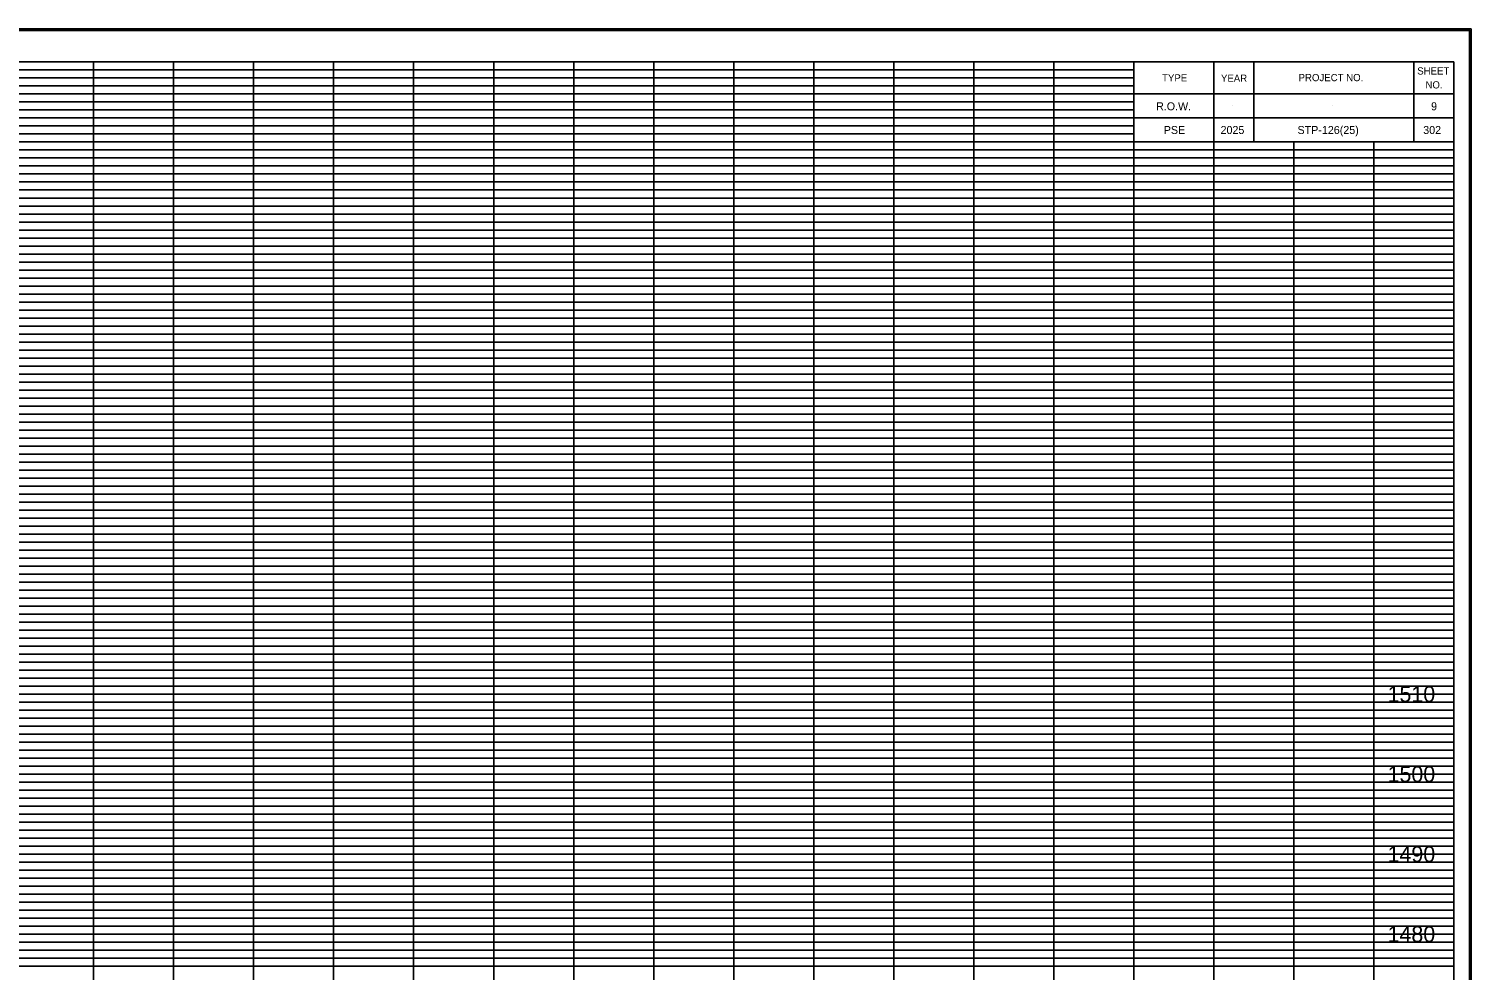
# Model space of a CAD drawing. Extents: x 980 to 2064, y 978 to 2267.
# Drawn here: x 1511.9 to 1692.2, y 1876.5 to 1994.1 of the extents above; entities that cross this region are included whole.
import ezdxf

# ---------------------------------------------------------------- set-up
doc = ezdxf.new("R2010")
doc.units = 0
for name, color, linetype in [('Default', 7, 'Continuous'), ('DESIGN - SCRATCH - User 1', 7, 'Continuous'), ('DESIGN - SHEET - Corner Text', 7, 'Continuous'), ('DESIGN - SHEET - Light Grid', 7, 'Continuous'), ('DESIGN - SHEET - Linework', 7, 'Continuous'), ('DESIGN - SHEET - Plot Shape', 7, 'Continuous')]:
    doc.layers.add(name, color=color, linetype=linetype)

# ---------------------------------------------------------------- blocks, each defined once
blk = doc.blocks.new('XSTSHT')
at = {"layer": 'DESIGN - SCRATCH - User 1'}
for p, q in [((28.5, 20.45), (28.5, 20.45)), ((29.24, 20.45), (29.24, 20.45)), ((30.49, 20.45), (30.49, 20.45)), ((31.74, 20.45), (31.74, 20.45)), ((28.5, 20.15), (28.5, 20.15)), ((29.24, 20.15), (29.24, 20.15)), ((30.49, 20.15), (30.49, 20.15)), ((31.74, 20.15), (31.74, 20.15))]:
    blk.add_line(p, q, dxfattribs=at)
at = {"layer": 'DESIGN - SHEET - Light Grid'}
for p, q in [((8, 20.9), (16, 20.9)), ((8, 20.8), (16, 20.8)), ((16, 20.9), (24, 20.9)), ((16, 20.8), (24, 20.8)), ((24, 20.9), (28, 20.9)), ((24, 20.8), (28, 20.8)), ((8, 20.7), (16, 20.7)), ((8, 20.6), (16, 20.6)), ((16, 20.7), (24, 20.7)), ((16, 20.6), (24, 20.6)), ((24, 20.7), (28, 20.7)), ((24, 20.6), (28, 20.6)), ((8, 20.5), (16, 20.5)), ((8, 20.4), (16, 20.4)), ((16, 20.5), (24, 20.5)), ((16, 20.4), (24, 20.4)), ((24, 20.5), (28, 20.5)), ((24, 20.4), (28, 20.4)), ((8, 20.3), (16, 20.3)), ((8, 20.2), (16, 20.2)), ((16, 20.3), (24, 20.3)), ((16, 20.2), (24, 20.2)), ((24, 20.3), (28, 20.3)), ((24, 20.2), (28, 20.2)), ((8, 20.1), (16, 20.1)), ((16, 20.1), (24, 20.1)), ((24, 20.1), (28, 20.1)), ((8, 19.9), (16, 19.9)), ((16, 19.9), (24, 19.9)), ((24, 19.9), (32, 19.9)), ((8, 19.8), (16, 19.8)), ((8, 19.7), (16, 19.7)), ((16, 19.8), (24, 19.8)), ((16, 19.7), (24, 19.7)), ((24, 19.8), (32, 19.8)), ((24, 19.7), (32, 19.7)), ((8, 19.6), (16, 19.6)), ((8, 19.5), (16, 19.5)), ((16, 19.6), (24, 19.6)), ((16, 19.5), (24, 19.5)), ((24, 19.6), (32, 19.6)), ((24, 19.5), (32, 19.5)), ((8, 19.4), (16, 19.4)), ((8, 19.3), (16, 19.3)), ((16, 19.4), (24, 19.4)), ((16, 19.3), (24, 19.3)), ((24, 19.4), (32, 19.4)), ((24, 19.3), (32, 19.3)), ((8, 19.2), (16, 19.2)), ((16, 19.2), (24, 19.2)), ((24, 19.2), (32, 19.2)), ((8, 19.1), (16, 19.1)), ((16, 19.1), (24, 19.1)), ((24, 19.1), (32, 19.1)), ((8, 18.9), (16, 18.9)), ((8, 18.8), (16, 18.8)), ((16, 18.9), (24, 18.9)), ((16, 18.8), (24, 18.8)), ((24, 18.9), (32, 18.9)), ((24, 18.8), (32, 18.8)), ((8, 18.7), (16, 18.7)), ((8, 18.6), (16, 18.6)), ((16, 18.7), (24, 18.7)), ((16, 18.6), (24, 18.6)), ((24, 18.7), (32, 18.7)), ((24, 18.6), (32, 18.6)), ((8, 18.5), (16, 18.5)), ((8, 18.4), (16, 18.4)), ((16, 18.5), (24, 18.5)), ((16, 18.4), (24, 18.4)), ((24, 18.5), (32, 18.5)), ((24, 18.4), (32, 18.4)), ((8, 18.3), (16, 18.3)), ((16, 18.3), (24, 18.3)), ((24, 18.3), (32, 18.3)), ((8, 18.2), (16, 18.2)), ((8, 18.1), (16, 18.1)), ((16, 18.2), (24, 18.2)), ((16, 18.1), (24, 18.1)), ((24, 18.2), (32, 18.2)), ((24, 18.1), (32, 18.1)), ((8, 17.9), (16, 17.9)), ((16, 17.9), (24, 17.9)), ((24, 17.9), (32, 17.9)), ((8, 17.8), (16, 17.8)), ((8, 17.7), (16, 17.7)), ((16, 17.8), (24, 17.8)), ((16, 17.7), (24, 17.7)), ((24, 17.8), (32, 17.8)), ((24, 17.7), (32, 17.7)), ((8, 17.6), (16, 17.6)), ((8, 17.5), (16, 17.5)), ((16, 17.6), (24, 17.6)), ((16, 17.5), (24, 17.5)), ((24, 17.6), (32, 17.6)), ((24, 17.5), (32, 17.5)), ((8, 17.4), (16, 17.4)), ((16, 17.4), (24, 17.4)), ((24, 17.4), (32, 17.4)), ((8, 17.3), (16, 17.3)), ((8, 17.2), (16, 17.2)), ((16, 17.3), (24, 17.3)), ((16, 17.2), (24, 17.2)), ((24, 17.3), (32, 17.3)), ((24, 17.2), (32, 17.2)), ((8, 17.1), (16, 17.1)), ((16, 17.1), (24, 17.1)), ((24, 17.1), (32, 17.1)), ((8, 16.9), (16, 16.9)), ((8, 16.8), (16, 16.8)), ((16, 16.9), (24, 16.9)), ((16, 16.8), (24, 16.8)), ((24, 16.9), (32, 16.9)), ((24, 16.8), (32, 16.8)), ((8, 16.7), (16, 16.7)), ((8, 16.6), (16, 16.6)), ((16, 16.7), (24, 16.7)), ((16, 16.6), (24, 16.6)), ((24, 16.7), (32, 16.7)), ((24, 16.6), (32, 16.6)), ((8, 16.5), (16, 16.5)), ((16, 16.5), (24, 16.5)), ((24, 16.5), (32, 16.5)), ((8, 16.4), (16, 16.4)), ((8, 16.3), (16, 16.3)), ((16, 16.4), (24, 16.4)), ((16, 16.3), (24, 16.3)), ((24, 16.4), (32, 16.4)), ((24, 16.3), (32, 16.3)), ((8, 16.2), (16, 16.2)), ((8, 16.1), (16, 16.1)), ((16, 16.2), (24, 16.2)), ((16, 16.1), (24, 16.1)), ((24, 16.2), (32, 16.2)), ((24, 16.1), (32, 16.1)), ((8, 15.9), (16, 15.9)), ((16, 15.9), (24, 15.9)), ((24, 15.9), (32, 15.9)), ((8, 15.8), (16, 15.8)), ((8, 15.7), (16, 15.7)), ((16, 15.8), (24, 15.8)), ((16, 15.7), (24, 15.7)), ((24, 15.8), (32, 15.8)), ((24, 15.7), (32, 15.7)), ((8, 15.6), (16, 15.6)), ((16, 15.6), (24, 15.6)), ((24, 15.6), (32, 15.6)), ((8, 15.5), (16, 15.5)), ((8, 15.4), (16, 15.4)), ((16, 15.5), (24, 15.5)), ((16, 15.4), (24, 15.4)), ((24, 15.5), (32, 15.5)), ((24, 15.4), (32, 15.4)), ((8, 15.3), (16, 15.3)), ((8, 15.2), (16, 15.2)), ((16, 15.3), (24, 15.3)), ((16, 15.2), (24, 15.2)), ((24, 15.3), (32, 15.3)), ((24, 15.2), (32, 15.2)), ((8, 15.1), (16, 15.1)), ((16, 15.1), (24, 15.1)), ((24, 15.1), (32, 15.1)), ((8, 14.9), (16, 14.9)), ((8, 14.8), (16, 14.8)), ((16, 14.9), (24, 14.9)), ((16, 14.8), (24, 14.8)), ((24, 14.9), (32, 14.9)), ((24, 14.8), (32, 14.8)), ((8, 14.7), (16, 14.7)), ((16, 14.7), (24, 14.7)), ((24, 14.7), (32, 14.7)), ((8, 14.6), (16, 14.6)), ((8, 14.5), (16, 14.5)), ((16, 14.6), (24, 14.6)), ((16, 14.5), (24, 14.5)), ((24, 14.6), (32, 14.6)), ((24, 14.5), (32, 14.5)), ((8, 14.4), (16, 14.4)), ((8, 14.3), (16, 14.3)), ((16, 14.4), (24, 14.4)), ((16, 14.3), (24, 14.3)), ((24, 14.4), (32, 14.4)), ((24, 14.3), (32, 14.3)), ((8, 14.2), (16, 14.2)), ((8, 14.1), (16, 14.1)), ((16, 14.2), (24, 14.2)), ((16, 14.1), (24, 14.1)), ((24, 14.2), (32, 14.2)), ((24, 14.1), (32, 14.1)), ((8, 13.9), (16, 13.9)), ((16, 13.9), (24, 13.9)), ((24, 13.9), (32, 13.9)), ((8, 13.8), (16, 13.8)), ((16, 13.8), (24, 13.8)), ((24, 13.8), (32, 13.8)), ((8, 13.7), (16, 13.7)), ((8, 13.6), (16, 13.6)), ((16, 13.7), (24, 13.7)), ((16, 13.6), (24, 13.6)), ((24, 13.7), (32, 13.7)), ((24, 13.6), (32, 13.6)), ((8, 13.5), (16, 13.5)), ((8, 13.4), (16, 13.4)), ((16, 13.5), (24, 13.5)), ((16, 13.4), (24, 13.4)), ((24, 13.5), (32, 13.5)), ((24, 13.4), (32, 13.4)), ((8, 13.3), (16, 13.3)), ((8, 13.2), (16, 13.2)), ((16, 13.3), (24, 13.3)), ((16, 13.2), (24, 13.2)), ((24, 13.3), (32, 13.3)), ((24, 13.2), (32, 13.2)), ((8, 13.1), (16, 13.1)), ((16, 13.1), (24, 13.1)), ((24, 13.1), (32, 13.1)), ((8, 12.9), (16, 12.9)), ((8, 12.8), (16, 12.8)), ((16, 12.9), (24, 12.9)), ((16, 12.8), (24, 12.8)), ((24, 12.9), (32, 12.9)), ((24, 12.8), (32, 12.8)), ((8, 12.7), (16, 12.7)), ((16, 12.7), (24, 12.7)), ((24, 12.7), (32, 12.7)), ((8, 12.6), (16, 12.6)), ((8, 12.5), (16, 12.5)), ((16, 12.6), (24, 12.6)), ((16, 12.5), (24, 12.5)), ((24, 12.6), (32, 12.6)), ((24, 12.5), (32, 12.5)), ((8, 12.4), (16, 12.4)), ((8, 12.3), (16, 12.3)), ((16, 12.4), (24, 12.4)), ((16, 12.3), (24, 12.3)), ((24, 12.4), (32, 12.4)), ((24, 12.3), (32, 12.3)), ((8, 12.2), (16, 12.2)), ((8, 12.1), (16, 12.1)), ((16, 12.2), (24, 12.2)), ((16, 12.1), (24, 12.1)), ((24, 12.2), (32, 12.2)), ((24, 12.1), (32, 12.1)), ((8, 11.9), (16, 11.9)), ((16, 11.9), (24, 11.9)), ((24, 11.9), (32, 11.9)), ((8, 11.8), (16, 11.8)), ((16, 11.8), (24, 11.8)), ((24, 11.8), (32, 11.8)), ((8, 11.7), (16, 11.7)), ((8, 11.6), (16, 11.6)), ((16, 11.7), (24, 11.7)), ((16, 11.6), (24, 11.6)), ((24, 11.7), (32, 11.7)), ((24, 11.6), (32, 11.6)), ((8, 11.5), (16, 11.5)), ((8, 11.4), (16, 11.4)), ((16, 11.5), (24, 11.5)), ((16, 11.4), (24, 11.4)), ((24, 11.5), (32, 11.5)), ((24, 11.4), (32, 11.4)), ((8, 11.3), (16, 11.3)), ((8, 11.2), (16, 11.2)), ((16, 11.3), (24, 11.3)), ((16, 11.2), (24, 11.2)), ((24, 11.3), (32, 11.3)), ((24, 11.2), (32, 11.2)), ((8, 11.1), (16, 11.1)), ((16, 11.1), (24, 11.1)), ((24, 11.1), (32, 11.1)), ((8, 10.9), (16, 10.9)), ((16, 10.9), (24, 10.9)), ((24, 10.9), (32, 10.9)), ((8, 10.8), (16, 10.8)), ((8, 10.7), (16, 10.7)), ((16, 10.8), (24, 10.8)), ((16, 10.7), (24, 10.7)), ((24, 10.8), (32, 10.8)), ((24, 10.7), (32, 10.7)), ((8, 10.6), (16, 10.6)), ((8, 10.5), (16, 10.5)), ((16, 10.6), (24, 10.6)), ((16, 10.5), (24, 10.5)), ((24, 10.6), (32, 10.6)), ((24, 10.5), (32, 10.5)), ((8, 10.4), (16, 10.4)), ((8, 10.3), (16, 10.3)), ((16, 10.4), (24, 10.4)), ((16, 10.3), (24, 10.3)), ((24, 10.4), (32, 10.4)), ((24, 10.3), (32, 10.3)), ((8, 10.2), (16, 10.2)), ((8, 10.1), (16, 10.1)), ((16, 10.2), (24, 10.2)), ((16, 10.1), (24, 10.1)), ((24, 10.2), (32, 10.2)), ((24, 10.1), (32, 10.1)), ((8, 9.9), (16, 9.9)), ((8, 9.8), (16, 9.8)), ((16, 9.9), (24, 9.9)), ((16, 9.8), (24, 9.8)), ((24, 9.9), (32, 9.9)), ((24, 9.8), (32, 9.8)), ((8, 9.7), (16, 9.7)), ((16, 9.7), (24, 9.7)), ((24, 9.7), (32, 9.7))]:
    blk.add_line(p, q, dxfattribs=at)
at = {"layer": 'DESIGN - SHEET - Linework'}
for p, q in [((-1.823, 21.414), (32.217, 21.414)), ((32.217, 21.414), (32.217, -0.414)), ((15, 0), (15, 21)), ((16, 0), (16, 21)), ((17, 0), (17, 21)), ((18, 0), (18, 21)), ((19, 0), (19, 21)), ((20, 0), (20, 21)), ((21, 0), (21, 21)), ((22, 0), (22, 21)), ((23, 0), (23, 21)), ((24, 0), (24, 21)), ((25, 0), (25, 21)), ((26, 0), (26, 21)), ((27, 0), (27, 21)), ((0, 20), (28, 20)), ((28, 0), (28, 20)), ((29, 0), (29, 20)), ((30, 0), (30, 20)), ((31, 0), (31, 20)), ((0, 19), (32, 19)), ((0, 18), (32, 18)), ((0, 17), (32, 17)), ((0, 16), (32, 16)), ((0, 15), (32, 15)), ((0, 14), (32, 14)), ((0, 13), (32, 13)), ((0, 12), (32, 12)), ((0, 11), (32, 11)), ((0, 10), (32, 10))]:
    blk.add_line(p, q, dxfattribs=at)
for points in [[(0, 21), (0, 0), (32, 0), (32, 21), (0, 21)], [(28, 21), (28, 20), (32, 20), (32, 21), (31.5, 21), (31.5, 20), (29.5, 20), (29.5, 21), (29, 21), (29, 20), (32, 20), (28, 20), (28, 20.3), (32, 20.3), (32, 20.6), (28, 20.6)]]:
    blk.add_lwpolyline(points, dxfattribs=at)
at = {"layer": 'DESIGN - SHEET - Plot Shape'}
for points in [[(-1.803, 21.394), (32.197, 21.394), (32.197, -0.394), (-1.803, -0.394)], [(-0.85, 21), (32, 21), (32, -0.25), (-0.85, -0.25)]]:
    blk.add_lwpolyline(points, close=True, dxfattribs=at)
at = {"layer": 'DESIGN - SHEET - Corner Text'}
for s, p in [('SHEET', (31.543, 20.843)), ('TYPE', (28.354, 20.756)), ('YEAR', (29.09, 20.752)), ('PROJECT NO.', (30.06, 20.76)), ('NO.', (31.646, 20.669))]:
    blk.add_text(s, height=0.09, dxfattribs=at).set_placement(p)

msp = doc.modelspace()

# ---------------------------------------------------------------- block references
at = {"layer": 'Default', "xscale": 10, "yscale": 10}
msp.add_blockref('XSTSHT', (1370, 1780), dxfattribs=at)

# ---------------------------------------------------------------- texts
at = {"layer": 'Default'}
for s, p in [('     1510     ', (1678.01, 1910)), ('     1500     ', (1678.01, 1900)), ('     1490     ', (1678.01, 1890)), ('     1480     ', (1678.01, 1880))]:
    msp.add_text(s, height=2, dxfattribs=at).set_placement(p)
at = {"layer": 'DESIGN - SHEET - Corner Text'}
for s, p in [('R.O.W.', (1652.79, 1983.96)), ('9', (1687.16, 1983.96)), ('PSE', (1653.75, 1981)), ('2025', (1660.85, 1981)), ('STP-126(25)', (1670.47, 1981)), ('302', (1686.18, 1981))]:
    msp.add_text(s, height=1, dxfattribs=at).set_placement(p)

doc.saveas('drawing.dxf')
